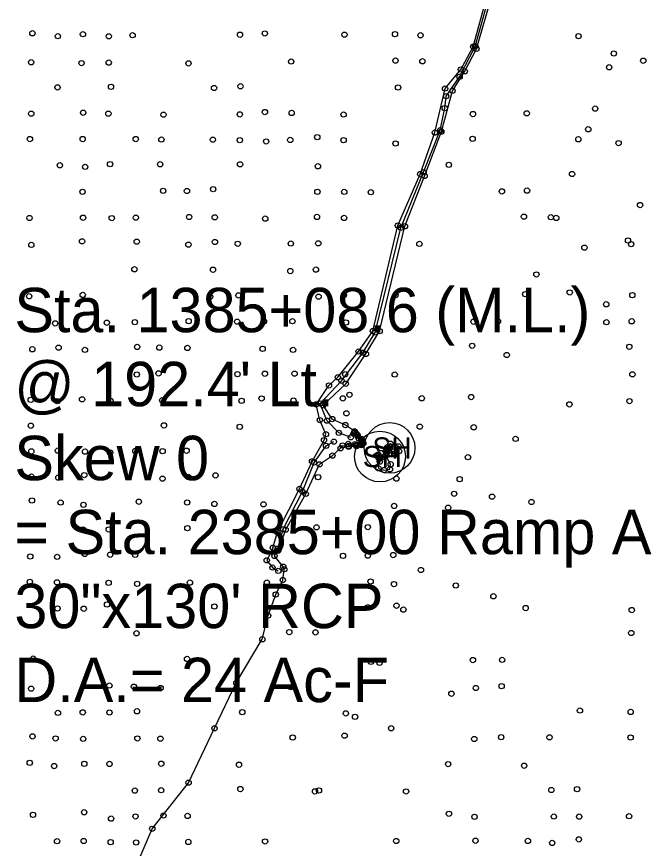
# Model space of a CAD drawing. Extents: x 20503438 to 20508873, y 7964251 to 7984667.
# Drawn here: x 20506298.3 to 20506538.4, y 7971184.4 to 7971499.2 of the extents above; entities that cross this region are included whole.
import ezdxf

# ---------------------------------------------------------------- set-up
doc = ezdxf.new("R2010")
doc.units = 0
for name, color, linetype in [('SurBreakLine', 7, 'Continuous'), ('SurConcreteSlab', 7, 'Continuous'), ('SurDrainageArrowDown', 7, 'Continuous'), ('SurNaturalCells', 7, 'Continuous'), ('SurPointsNonDTM', 7, 'Continuous'), ('SurSurveyPoints', 7, 'Continuous'), ('SurTxtDrainage', 7, 'Continuous')]:
    doc.layers.add(name, color=color, linetype=linetype)

msp = doc.modelspace()

# ---------------------------------------------------------------- linework, layer by layer
at = {"layer": 'SurBreakLine'}
for points in [[(20506395.2, 7971298.18), (20506396.94, 7971304.01), (20506405.3, 7971320.42), (20506410.06, 7971330.84), (20506414.58, 7971338.9), (20506415.3, 7971341.14), (20506412.99, 7971346.47), (20506411.64, 7971352.44), (20506416.46, 7971359.59), (20506419.82, 7971362.68), (20506427.67, 7971372.42), (20506433.06, 7971380.19), (20506442.53, 7971420.12), (20506450.97, 7971439.6), (20506456.56, 7971455.3), (20506460.39, 7971471.96), (20506466.37, 7971479.16), (20506471.04, 7971487.78), (20506476.09, 7971506.26)], [(20506397.24, 7971297.03), (20506400.08, 7971305.02), (20506407.67, 7971318.56), (20506412.86, 7971329.74), (20506417.74, 7971333.04), (20506420.81, 7971335.82), (20506421.57, 7971336.86), (20506423.9, 7971336.46), (20506426.86, 7971336.6), (20506428.7, 7971337.01), (20506429.43, 7971337.72), (20506429.18, 7971338.57), (20506428.72, 7971339.33), (20506427.27, 7971340.87), (20506426.8, 7971341.39), (20506426.14, 7971342.27), (20506422.65, 7971344.59), (20506417.7, 7971346.87), (20506414.24, 7971352.09), (20506422.79, 7971360.24), (20506430.44, 7971371.5), (20506435.62, 7971380.13), (20506445.2, 7971419.84), (20506452.65, 7971438.86), (20506458.97, 7971455.68), (20506463.19, 7971471.1), (20506467.81, 7971478.51), (20506472.22, 7971486.98), (20506477.73, 7971505.73)], [(20506441.19, 7971333.56), (20506443, 7971334.7), (20506442.71, 7971336.56), (20506439.76, 7971337.56), (20506438.51, 7971336.22), (20506438, 7971334.81), (20506439.59, 7971333.79)], [(20506438.45, 7971335.42), (20506439.52, 7971336.57), (20506440.76, 7971335.49), (20506439.11, 7971334.83)], [(20506436.07, 7971334), (20506434.4, 7971333.04), (20506435.16, 7971328.22), (20506437.35, 7971327.56), (20506439.53, 7971327.85), (20506439.79, 7971329.76), (20506437.98, 7971332.91)], [(20506435.08, 7971333.41), (20506437.11, 7971332.44), (20506435.69, 7971330.78), (20506435.31, 7971332.06), (20506434.74, 7971332.92)], [(20506395.2, 7971298.18), (20506392.91, 7971293.4), (20506395.07, 7971290.67), (20506397.26, 7971289.41)]]:
    msp.add_lwpolyline(points, dxfattribs=at)
at = {"layer": 'SurConcreteSlab'}
msp.add_lwpolyline([(20506425.77, 7971341.38), (20506427.75, 7971339.51), (20506429.04, 7971338.19), (20506428.52, 7971337.52), (20506426.41, 7971337.39), (20506423.76, 7971337.46), (20506423.9, 7971336.69), (20506426.95, 7971337.05), (20506428.52, 7971337.25), (20506429.11, 7971338.1), (20506428.98, 7971338.69), (20506427.4, 7971340.38), (20506426.02, 7971341.84)], close=True, dxfattribs=at)
at = {"layer": 'SurDrainageArrowDown'}
for points in [[(20506424.71, 7971339.95), (20506420.17, 7971341.66), (20506415.68, 7971346.3), (20506413.18, 7971352.74), (20506421.18, 7971361.4), (20506429.25, 7971371.98), (20506433.94, 7971379.61), (20506443.68, 7971419.25), (20506452.24, 7971440.3), (20506458.59, 7971456.18), (20506460.25, 7971464.53), (20506460.79, 7971469.07), (20506465.89, 7971476.4), (20506471.8, 7971487.93), (20506476.84, 7971506)], [(20506341.24, 7971172.37), (20506349.6, 7971191.81), (20506363.34, 7971209.26), (20506373.16, 7971229.84), (20506381.4, 7971247.03), (20506391.24, 7971263.52), (20506393.46, 7971272.51), (20506396.3, 7971280.47), (20506398.99, 7971285.94), (20506399.54, 7971290.04), (20506399.17, 7971291), (20506395.85, 7971295.06), (20506397.06, 7971297.8), (20506399.12, 7971305.17), (20506406.46, 7971319.4), (20506410.82, 7971330.46), (20506415.36, 7971336.75), (20506418.32, 7971338.32)]]:
    msp.add_lwpolyline(points, dxfattribs=at)
at = {"layer": 'SurNaturalCells'}
for centre in [(20506439.4, 7971335.94), (20506435.76, 7971332.7)]:
    msp.add_circle(centre, 9.59, dxfattribs=at)
at = {"layer": 'SurPointsNonDTM'}
msp.add_circle((20506478.16, 7971317.51), 1, dxfattribs=at)
at = {"layer": 'SurSurveyPoints'}
for centre in [(20506304.24, 7971492.89), (20506323.38, 7971492.52), (20506342.15, 7971492.15), (20506382.8, 7971492.32), (20506392.18, 7971492.82), (20506422.33, 7971492.35), (20506441.43, 7971492.55), (20506451.11, 7971492.13), (20506313.89, 7971491.77), (20506333.15, 7971491.73), (20506510.88, 7971491.8), (20506471.04, 7971487.78), (20506471.8, 7971487.93), (20506472.22, 7971486.98), (20506441.62, 7971482.55), (20506524.24, 7971485.22), (20506535.36, 7971482.48), (20506303.76, 7971481.91), (20506322.85, 7971481.59), (20506333.14, 7971481.77), (20506363.29, 7971481.47), (20506402.14, 7971482.18), (20506451.8, 7971482.3), (20506522.48, 7971480.01), (20506465.89, 7971476.4), (20506466.37, 7971479.16), (20506467.81, 7971478.51), (20506313.76, 7971472.4), (20506333.99, 7971472.6), (20506372.98, 7971472.17), (20506382.97, 7971472.81), (20506442.61, 7971472.36), (20506460.39, 7971471.96), (20506463.19, 7971471.1), (20506460.79, 7971469.07), (20506460.25, 7971464.53), (20506517.19, 7971464.36), (20506303.81, 7971462.46), (20506323.46, 7971462.82), (20506332.99, 7971462.45), (20506353.83, 7971462.07), (20506382.71, 7971462.18), (20506392.23, 7971463.07), (20506402.34, 7971462.73), (20506422, 7971462.12), (20506470.94, 7971462.3), (20506491.27, 7971462.59), (20506456.56, 7971455.3), (20506458.59, 7971456.18), (20506458.97, 7971455.68), (20506514.55, 7971456.54), (20506303.31, 7971452.85), (20506323.27, 7971452.83), (20506343.35, 7971452.85), (20506353.06, 7971452.66), (20506372.53, 7971452.61), (20506382.72, 7971452.43), (20506392.68, 7971451.94), (20506401.81, 7971452.5), (20506412.03, 7971453.55), (20506421.98, 7971452.42), (20506441.66, 7971451.16), (20506470.8, 7971452.94), (20506510.81, 7971452.78), (20506526.04, 7971451.31), (20506314.63, 7971442.92), (20506324.21, 7971442.31), (20506333.63, 7971443.33), (20506352.6, 7971443.3), (20506382.83, 7971443.28), (20506412.27, 7971442.54), (20506461.83, 7971443.1), (20506450.97, 7971439.6), (20506452.24, 7971440.3), (20506452.65, 7971438.86), (20506508.43, 7971439.62), (20506323.22, 7971432.87), (20506353.72, 7971433.24), (20506362.71, 7971433.19), (20506372.64, 7971433.89), (20506412.09, 7971432.88), (20506422.24, 7971432.85), (20506432.3, 7971432.73), (20506481.9, 7971433.04), (20506491.39, 7971433.34), (20506534.17, 7971427.86), (20506303.15, 7971422.96), (20506323.41, 7971423.06), (20506334.27, 7971422.93), (20506343.4, 7971423.09), (20506363.57, 7971423.35), (20506373.24, 7971423.22), (20506392.36, 7971422.74), (20506411.92, 7971423.37), (20506422.18, 7971422.99), (20506490.22, 7971423.48), (20506500.42, 7971423.27), (20506502.46, 7971423), (20506442.53, 7971420.12), (20506445.2, 7971419.84), (20506443.68, 7971419.25), (20506323.05, 7971414.13), (20506343.73, 7971414.01), (20506373.32, 7971413.89), (20506381.95, 7971413.21), (20506402.03, 7971413.3), (20506412.41, 7971413.38), (20506450.68, 7971413.17), (20506529.6, 7971414.45), (20506303.84, 7971412.79), (20506363.27, 7971412.87), (20506513.11, 7971411.74), (20506530.77, 7971413.06), (20506342.85, 7971403.57), (20506372.58, 7971403.4), (20506401.83, 7971402.9), (20506411.53, 7971403.44), (20506494.93, 7971401.61), (20506507.56, 7971394.79), (20506303.05, 7971393.35), (20506323.28, 7971393.86), (20506371.53, 7971393.2), (20506382.23, 7971393.67), (20506412.53, 7971393.19), (20506422.07, 7971393.74), (20506441.65, 7971393.77), (20506490.74, 7971394.13), (20506531.24, 7971393.76), (20506521.37, 7971390.32), (20506312.88, 7971383.07), (20506332.41, 7971383.33), (20506343, 7971383.54), (20506363.38, 7971383.93), (20506381.7, 7971383.74), (20506391.87, 7971383.89), (20506402.61, 7971383.91), (20506422.89, 7971383.42), (20506471.18, 7971383.71), (20506480.4, 7971383.86), (20506521.41, 7971383.53), (20506530.99, 7971383.88), (20506433.06, 7971380.19), (20506433.94, 7971379.61), (20506435.62, 7971380.13), (20506304.22, 7971373.3), (20506314.17, 7971373.89), (20506324.13, 7971373.05), (20506343.88, 7971374.16), (20506352.27, 7971373.92), (20506362.88, 7971373.79), (20506391.36, 7971373.46), (20506402.87, 7971373.05), (20506427.67, 7971372.42), (20506470.61, 7971374.61), (20506530.09, 7971374.23), (20506429.25, 7971371.98), (20506430.44, 7971371.5), (20506483.71, 7971371.11), (20506343.74, 7971363.75), (20506351.99, 7971364.15), (20506381.84, 7971363.86), (20506392.23, 7971364.02), (20506403.45, 7971364.05), (20506422.56, 7971363.82), (20506441.34, 7971363.72), (20506531.25, 7971363.81), (20506419.82, 7971362.68), (20506421.18, 7971361.4), (20506422.79, 7971360.24), (20506416.46, 7971359.59), (20506303.61, 7971354.14), (20506313.65, 7971353.65), (20506323.04, 7971354.34), (20506333.76, 7971353.77), (20506353.38, 7971353.99), (20506383.41, 7971353.77), (20506390.98, 7971354.68), (20506403.02, 7971353.89), (20506421.69, 7971354.69), (20506424.21, 7971356.06), (20506451.56, 7971354.73), (20506470.24, 7971355.21), (20506530.14, 7971353.67), (20506411.64, 7971352.44), (20506413.18, 7971352.74), (20506414.24, 7971352.09), (20506507.43, 7971352.43), (20506423.06, 7971349.05), (20506303.67, 7971344.35), (20506354.03, 7971344.48), (20506382.69, 7971343.94), (20506412.99, 7971346.47), (20506415.68, 7971346.3), (20506417.7, 7971346.87), (20506422.65, 7971344.59), (20506450.8, 7971344), (20506415.3, 7971341.14), (20506420.17, 7971341.66), (20506425.77, 7971341.38), (20506426.02, 7971341.84), (20506426.14, 7971342.27), (20506426.8, 7971341.39), (20506427.27, 7971340.87), (20506471.22, 7971343.78), (20506414.58, 7971338.9), (20506418.32, 7971338.32), (20506424.71, 7971339.95), (20506427.4, 7971340.38), (20506427.75, 7971339.51), (20506428.72, 7971339.33), (20506428.98, 7971338.69), (20506429.04, 7971338.19), (20506429.11, 7971338.1), (20506429.18, 7971338.57), (20506429.43, 7971337.72), (20506487.08, 7971339.37), (20506303.85, 7971334.65), (20506313.9, 7971334.95), (20506324.16, 7971334.56), (20506343.2, 7971334.8), (20506353.52, 7971334.73), (20506362.6, 7971334.88), (20506415.36, 7971336.75), (20506420.81, 7971335.82), (20506421.57, 7971336.86), (20506423.76, 7971337.46), (20506423.9, 7971336.69), (20506423.9, 7971336.46), (20506426.41, 7971337.39), (20506426.86, 7971336.6), (20506426.95, 7971337.05), (20506428.52, 7971337.52), (20506428.52, 7971337.25), (20506428.7, 7971337.01), (20506438, 7971334.81), (20506438.45, 7971335.42), (20506438.51, 7971336.22), (20506439.11, 7971334.83), (20506439.52, 7971336.57), (20506439.76, 7971337.56), (20506440.76, 7971335.49), (20506442.71, 7971336.56), (20506443, 7971334.7), (20506333.64, 7971334.22), (20506417.74, 7971333.04), (20506434.4, 7971333.04), (20506434.74, 7971332.92), (20506435.08, 7971333.41), (20506435.31, 7971332.06), (20506436.07, 7971334), (20506437.11, 7971332.44), (20506437.98, 7971332.91), (20506439.59, 7971333.79), (20506441.19, 7971333.56), (20506469.03, 7971332.43), (20506410.06, 7971330.84), (20506410.82, 7971330.46), (20506412.86, 7971329.74), (20506435.16, 7971328.22), (20506435.69, 7971330.78), (20506439.79, 7971329.76), (20506303.88, 7971325.12), (20506323.87, 7971325.66), (20506373.52, 7971325.55), (20506437.35, 7971327.56), (20506439.53, 7971327.85), (20506314.07, 7971324.69), (20506353.49, 7971324.31), (20506363.23, 7971324.97), (20506412.33, 7971324.87), (20506441.97, 7971324.34), (20506465.91, 7971324.13), (20506405.3, 7971320.42), (20506406.46, 7971319.4), (20506304.07, 7971316.05), (20506344.51, 7971315.59), (20506407.67, 7971318.56), (20506463.82, 7971318.59), (20506314.92, 7971315.28), (20506323.56, 7971314.4), (20506362.8, 7971315.29), (20506373.12, 7971314.76), (20506391.68, 7971314.6), (20506441.13, 7971313.99), (20506461.54, 7971313.34), (20506493.07, 7971315.49), (20506323.49, 7971305.05), (20506333.11, 7971305.1), (20506362.89, 7971305.59), (20506396.94, 7971304.01), (20506399.12, 7971305.17), (20506400.08, 7971305.02), (20506411.74, 7971305.89), (20506431.14, 7971305.98), (20506395.2, 7971298.18), (20506397.06, 7971297.8), (20506397.24, 7971297.03), (20506303.45, 7971294.87), (20506313.63, 7971294.71), (20506324.04, 7971295.8), (20506333.68, 7971295.52), (20506343.12, 7971295.5), (20506395.85, 7971295.06), (20506421.77, 7971295.12), (20506431.18, 7971295.19), (20506440.78, 7971295.41), (20506392.91, 7971293.4), (20506395.07, 7971290.67), (20506399.17, 7971291), (20506397.26, 7971289.41), (20506399.54, 7971290.04), (20506451.25, 7971289.74), (20506303.28, 7971285.27), (20506313.56, 7971285.08), (20506333.08, 7971284.9), (20506343.89, 7971284.51), (20506363.84, 7971284.99), (20506392.94, 7971285), (20506398.99, 7971285.94), (20506432.21, 7971285.39), (20506441.06, 7971284.4), (20506464.44, 7971283.88), (20506396.3, 7971280.47), (20506478.66, 7971279.81), (20506313.76, 7971275.19), (20506323.68, 7971275.08), (20506332.48, 7971276.68), (20506373.1, 7971275.94), (20506431.12, 7971275.6), (20506442, 7971276.24), (20506444.61, 7971274.76), (20506490.88, 7971275.33), (20506393.46, 7971272.51), (20506531.01, 7971274.59), (20506343.64, 7971265.8), (20506401.45, 7971266.24), (20506411.35, 7971266.12), (20506530.84, 7971265.91), (20506391.24, 7971263.52), (20506304.56, 7971256.23), (20506362.78, 7971256.09), (20506481.97, 7971255.73), (20506432.33, 7971255), (20506435.59, 7971254.61), (20506470.93, 7971255.65), (20506381.4, 7971247.03), (20506303.76, 7971244.84), (20506333.38, 7971246.02), (20506342.67, 7971245.56), (20506352.75, 7971245.07), (20506402.02, 7971245.38), (20506472.03, 7971245.08), (20506481.77, 7971245.79), (20506462.77, 7971242.92), (20506313.9, 7971235.67), (20506323.29, 7971235.85), (20506333.4, 7971235.82), (20506343.83, 7971236.28), (20506383.64, 7971235.93), (20506422.85, 7971235.49), (20506426.32, 7971234.18), (20506511.4, 7971236.55), (20506530.61, 7971236.04), (20506373.16, 7971229.84), (20506440, 7971229.86), (20506304.29, 7971226.76), (20506313.04, 7971226), (20506323.48, 7971225.83), (20506343.98, 7971225.99), (20506352.68, 7971225.91), (20506402.73, 7971226.35), (20506422.36, 7971227.05), (20506471.44, 7971225.79), (20506481.61, 7971226.48), (20506499.89, 7971226.42), (20506530.58, 7971226.36), (20506303.25, 7971216.78), (20506312.48, 7971215.55), (20506323.89, 7971216.4), (20506333.41, 7971216.34), (20506353.02, 7971216.43), (20506382.41, 7971216.04), (20506461.57, 7971216.28), (20506490.33, 7971215.68), (20506363.34, 7971209.26), (20506343.01, 7971206.25), (20506352.96, 7971206.4), (20506382.93, 7971206.84), (20506411.17, 7971205.95), (20506412.68, 7971206.3), (20506445.63, 7971205.94), (20506500.59, 7971206.48), (20506510.32, 7971206.79), (20506304.47, 7971197.1), (20506323.86, 7971198.06), (20506343.28, 7971196.48), (20506353.85, 7971196.82), (20506362.96, 7971196.66), (20506461.84, 7971197.48), (20506471.53, 7971196.32), (20506501.55, 7971196.44), (20506511.13, 7971196.42), (20506530.01, 7971196.56), (20506334.02, 7971195.66), (20506349.6, 7971191.81), (20506313.57, 7971187.1), (20506323.64, 7971187.18), (20506333.86, 7971186.75), (20506343.52, 7971186.62), (20506363.25, 7971186.83), (20506392.28, 7971187.01), (20506441.91, 7971187.18), (20506471.89, 7971187.29), (20506491.74, 7971187.21), (20506511.01, 7971187.78), (20506500.92, 7971186.46)]:
    msp.add_circle(centre, 1, dxfattribs=at)

# ---------------------------------------------------------------- texts
at = {"layer": 'SurNaturalCells'}
for p in [(20506432.88, 7971331.94), (20506429.24, 7971328.7)]:
    msp.add_text('SH', height=7.995, rotation=360, dxfattribs=at).set_placement(p)
at = {"layer": 'SurTxtDrainage'}
for s, p in [('Sta. 1385+08.6 (M.L.)', (20506297.43, 7971379.74)), ("@ 192.4' Lt.", (20506297.43, 7971351.74)), ('Skew 0', (20506297.43, 7971323.74)), ('= Sta. 2385+00 Ramp A', (20506297.43, 7971295.74)), ('30"x130\' RCP', (20506297.43, 7971267.74)), ('D.A.= 24 Ac-F', (20506297.43, 7971239.74))]:
    msp.add_text(s, height=16.8, dxfattribs=at).set_placement(p)

doc.saveas('drawing.dxf')
